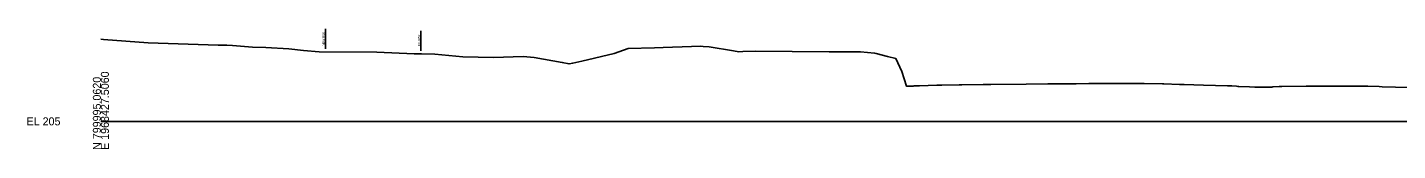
# Model space of a CAD drawing. Extents: x 1979833 to 1982361, y 790388 to 810009.
# Drawn here: x 1979832.9 to 1980312.1, y 803388 to 803430.1 of the extents above; entities that cross this region are included whole.
import ezdxf

# ---------------------------------------------------------------- set-up
doc = ezdxf.new("R2010")
doc.units = 0
for name, color, linetype in [('Default', 7, 'Continuous'), ('RD_GPK_XS_Cell', 7, 'Continuous'), ('RD_XS_ExGround', 7, 'Continuous'), ('RD_XS_ExRW', 7, 'Continuous'), ('RD_XS_NewRW', 7, 'Continuous')]:
    doc.layers.add(name, color=color, linetype=linetype)

msp = doc.modelspace()

# ---------------------------------------------------------------- linework, layer by layer
at = {"layer": 'RD_GPK_XS_Cell'}
msp.add_line((1979858.57, 803397.73), (1980358.57, 803397.73), dxfattribs=at)
at = {"layer": 'RD_XS_ExGround'}
msp.add_lwpolyline([(1979858.57, 803426.48), (1979859.49, 803426.43), (1979875.11, 803425.21), (1979899.63, 803424.45), (1979902.68, 803424.38), (1979904.58, 803424.29), (1979911.55, 803423.67), (1979916.31, 803423.55), (1979924.32, 803423.17), (1979929.41, 803422.57), (1979934.92, 803422.09), (1979955.11, 803421.95), (1979968.21, 803421.34), (1979970.74, 803421.39), (1979975.35, 803421.24), (1979985.16, 803420.28), (1979995.95, 803420.14), (1980006.27, 803420.4), (1980010.09, 803420.12), (1980019.97, 803418.38), (1980022.37, 803417.81), (1980023.62, 803418.13), (1980026.76, 803418.83), (1980038.16, 803421.46), (1980043.02, 803423.21), (1980052.24, 803423.49), (1980055.28, 803423.58), (1980065.14, 803423.95), (1980068.34, 803424.04), (1980069.26, 803423.98), (1980071.32, 803423.83), (1980079.88, 803422.4), (1980081.72, 803422.1), (1980083.11, 803422.14), (1980087.49, 803422.25), (1980113.37, 803422.03), (1980124.24, 803422.03), (1980129.18, 803421.61), (1980129.76, 803421.51), (1980133.67, 803420.49), (1980136.69, 803419.71), (1980138.76, 803415.24), (1980140.42, 803410), (1980141.06, 803410.01), (1980141.54, 803410.01), (1980142.71, 803410.07), (1980143.1, 803410.16), (1980144.89, 803410.19), (1980151.03, 803410.36), (1980152.77, 803410.39), (1980158.78, 803410.51), (1980159.68, 803410.53), (1980167.22, 803410.59), (1980169.91, 803410.6), (1980182.18, 803410.76), (1980189.83, 803410.85), (1980199.74, 803410.92), (1980204.18, 803410.96), (1980210.78, 803411), (1980211.16, 803411.01), (1980217.99, 803411.02), (1980220.75, 803411.01), (1980223.54, 803411), (1980229.86, 803410.83), (1980230.32, 803410.81), (1980235.88, 803410.67), (1980237.54, 803410.63), (1980244.3, 803410.44), (1980252.69, 803410.19), (1980254.21, 803410.11), (1980255.75, 803410.03), (1980256.32, 803409.91), (1980256.65, 803409.9), (1980260.31, 803409.76), (1980262.15, 803409.72), (1980263.8, 803409.7), (1980265.5, 803409.71), (1980268.14, 803409.75), (1980268.45, 803409.86), (1980270.72, 803409.92), (1980271.7, 803409.95), (1980280.15, 803410.01), (1980286.67, 803410.06), (1980288.08, 803410.07), (1980292, 803410.05), (1980293.64, 803410.04), (1980294.21, 803410.04), (1980300.72, 803410.01), (1980301.76, 803410.01), (1980305.69, 803409.88), (1980306.73, 803409.85), (1980316.08, 803409.59)], dxfattribs=at)
at = {"layer": 'RD_XS_ExRW'}
msp.add_line((1979970.53, 803422.39), (1979970.53, 803429.39), dxfattribs=at)
at = {"layer": 'RD_XS_NewRW'}
msp.add_line((1979937.11, 803423.08), (1979937.11, 803430.08), dxfattribs=at)

# ---------------------------------------------------------------- texts
at = {"layer": 'Default'}
msp.add_text('-', height=0.0001, dxfattribs=at).set_placement((1979858.57, 803397.73))
at = {"layer": 'RD_GPK_XS_Cell'}
for s, p in [('E 1968427.5060', (1979861.37, 803387.73)), ('N 799995.0620', (1979858.57, 803387.73))]:
    msp.add_text(s, height=2.8, rotation=90, dxfattribs=at).set_placement(p)
msp.add_text('EL 205', height=2.8, dxfattribs=at).set_placement((1979832.57, 803396.33))
at = {"layer": 'RD_XS_ExRW'}
msp.add_text('EX. R/W ', height=0.75, rotation=90, dxfattribs=at).set_placement((1979970.25, 803424.07))
at = {"layer": 'RD_XS_NewRW'}
msp.add_text('NEW R/W ', height=0.75, rotation=90, dxfattribs=at).set_placement((1979936.83, 803424.22))

doc.saveas('drawing.dxf')
